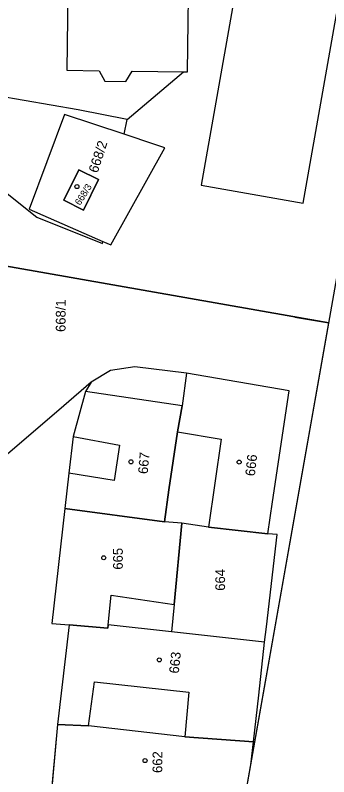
# Model space of a CAD drawing. Extents: x -534481 to -534262, y -1190577 to -1190138.
# Drawn here: x -534325.5 to -534298.1, y -1190410 to -1190343.4 of the extents above; entities that cross this region are included whole.
import ezdxf

# ---------------------------------------------------------------- set-up
doc = ezdxf.new("R2010")
doc.units = 0
for name, color, linetype in [('Definiční body', 7, 'Continuous'), ('Polygon budovy', 7, 'Continuous'), ('Polygon parcely', 7, 'Continuous'), ('Vrstva 30', 7, 'Continuous'), ('Vrstva 43', 7, 'Continuous'), ('Vrstva 46', 7, 'Continuous'), ('Značky bodu BP', 7, 'Continuous')]:
    doc.layers.add(name, color=color, linetype=linetype)

msp = doc.modelspace()

# ---------------------------------------------------------------- linework, layer by layer
at = {"layer": 'Definiční body'}
for p, q in [((-534315.98, -1190353.76), (-534315.73, -1190352.48)), ((-534310.54, -1190374.65), (-534315.06, -1190374.11)), ((-534310.54, -1190374.65), (-534310.94, -1190377.52)), ((-534301.59, -1190376.19), (-534310.54, -1190374.65)), ((-534312.48, -1190387.67), (-534321.18, -1190386.48)), ((-534310.97, -1190387.76), (-534312.48, -1190387.67)), ((-534310.97, -1190387.76), (-534311.63, -1190394.88)), ((-534311.63, -1190394.88), (-534311.85, -1190397.27)), ((-534320.78, -1190396.67), (-534321.81, -1190405.38)), ((-534303.73, -1190398.17), (-534311.85, -1190397.27)), ((-534321.81, -1190405.38), (-534322.86, -1190416.77))]:
    msp.add_line(p, q, dxfattribs=at)
for points in [[(-534315.73, -1190352.48), (-534310.81, -1190348.3), (-534310.45, -1190348.3), (-534310.32, -1190337.38), (-534310.32, -1190337.25)], [(-534315.73, -1190352.48), (-534320, -1190351.64), (-534327.1, -1190350.42), (-534332.53, -1190349.48)], [(-534315.98, -1190353.76), (-534321.21, -1190352.03), (-534324.29, -1190360.33), (-534317.85, -1190363.15)], [(-534332.65, -1190353.81), (-534323.62, -1190361.03), (-534317.88, -1190363.31), (-534317.85, -1190363.15)], [(-534317.85, -1190363.15), (-534317.16, -1190363.45), (-534312.43, -1190354.94), (-534313.32, -1190354.65), (-534315.98, -1190353.76)], [(-534318.22, -1190357.73), (-534319.55, -1190360.4), (-534321.26, -1190359.54), (-534319.94, -1190356.87), (-534318.22, -1190357.73)], [(-534315.06, -1190374.11), (-534317.18, -1190374.42), (-534318.86, -1190375.44)], [(-534318.86, -1190375.44), (-534321.27, -1190377.51), (-534326.78, -1190382.26), (-534328.4, -1190383.66)], [(-534318.86, -1190375.44), (-534319.37, -1190376.25), (-534320.44, -1190380.21), (-534320.81, -1190383.39), (-534321.18, -1190386.48)], [(-534303.44, -1190388.7), (-534303.03, -1190385.92), (-534301.59, -1190376.19)], [(-534310.94, -1190377.52), (-534311.35, -1190379.79), (-534312.08, -1190384.85), (-534312.48, -1190387.67)], [(-534321.18, -1190386.48), (-534322.3, -1190396.55), (-534320.78, -1190396.67)], [(-534303.44, -1190388.7), (-534308.63, -1190388.11), (-534310.97, -1190387.76)], [(-534303.73, -1190398.17), (-534303.58, -1190396.85), (-534302.64, -1190388.78), (-534303.44, -1190388.7)], [(-534311.85, -1190397.27), (-534317.4, -1190396.66), (-534317.42, -1190396.96), (-534320.78, -1190396.67)], [(-534304.7, -1190406.9), (-534304.25, -1190402.82), (-534303.73, -1190398.17)], [(-534304.7, -1190406.9), (-534310.69, -1190406.47), (-534319.12, -1190405.49), (-534321.81, -1190405.38)], [(-534304.949, -1190408.92), (-534304.7, -1190406.9)]]:
    msp.add_lwpolyline(points, dxfattribs=at)
at = {"layer": 'Polygon parcely'}
msp.add_line((-534306.696, -1190418.823), (-534304.949, -1190408.92), dxfattribs=at)
for points in [[(-534320.89, -1190337.07), (-534320.88, -1190337.18), (-534325.2, -1190337.17), (-534325.09, -1190341.34), (-534320.9, -1190341.35), (-534320.99, -1190348.17), (-534318.18, -1190348.21), (-534317.67, -1190349.12), (-534315.85, -1190349.15), (-534315.3, -1190348.25), (-534310.81, -1190348.3), (-534310.45, -1190348.3), (-534310.32, -1190337.38)], [(-534321.26, -1190359.54), (-534319.55, -1190360.4), (-534318.22, -1190357.73), (-534319.94, -1190356.87)], [(-534311.35, -1190379.79), (-534307.52, -1190380.43), (-534308.63, -1190388.11), (-534303.44, -1190388.7), (-534303.03, -1190385.92), (-534301.59, -1190376.19), (-534310.54, -1190374.65), (-534310.94, -1190377.52)], [(-534316.87, -1190384.03), (-534320.81, -1190383.39), (-534321.18, -1190386.48), (-534312.48, -1190387.67), (-534312.08, -1190384.85), (-534311.35, -1190379.79), (-534310.94, -1190377.52), (-534319.37, -1190376.25), (-534320.44, -1190380.21), (-534316.39, -1190380.95)], [(-534322.3, -1190396.55), (-534320.78, -1190396.67), (-534317.42, -1190396.96), (-534317.4, -1190396.66), (-534317.14, -1190394.07), (-534311.63, -1190394.88), (-534310.97, -1190387.76), (-534312.48, -1190387.67), (-534321.18, -1190386.48)], [(-534317.4, -1190396.66), (-534317.42, -1190396.96), (-534320.78, -1190396.67), (-534321.81, -1190405.38), (-534319.12, -1190405.49), (-534318.59, -1190401.64), (-534310.36, -1190402.55), (-534310.69, -1190406.47), (-534304.7, -1190406.9), (-534304.25, -1190402.82), (-534303.73, -1190398.17), (-534311.85, -1190397.27)]]:
    msp.add_lwpolyline(points, close=True, dxfattribs=at)
msp.add_lwpolyline([(-534304.949, -1190408.92), (-534304.7, -1190406.9), (-534310.69, -1190406.47), (-534319.12, -1190405.49), (-534321.81, -1190405.38), (-534322.86, -1190416.77), (-534319.66, -1190417.17), (-534318.89, -1190410.64), (-534311.23, -1190411.47), (-534311.53, -1190414.36), (-534313.6, -1190414.13), (-534314.01, -1190417.87), (-534306.696, -1190418.823)], dxfattribs=at)
at = {"layer": 'Vrstva 30'}
msp.add_line((-534316.367, -1190473.675), (-534298.134, -1190370.27), dxfattribs=at)
for points in [[(-534407.912, -1190137.674), (-534480.845, -1190551.293), (-534334.601, -1190577.08), (-534261.668, -1190163.461)], [(-534279.901, -1190266.866), (-534426.145, -1190241.079), (-534444.378, -1190344.484), (-534298.134, -1190370.27)], [(-534298.134, -1190370.27), (-534444.378, -1190344.484), (-534462.611, -1190447.888), (-534316.367, -1190473.675)]]:
    msp.add_lwpolyline(points, dxfattribs=at)
at = {"layer": 'Vrstva 43'}
msp.add_line((-534301.089, -1190369.749), (-534298.134, -1190370.27), dxfattribs=at)
msp.add_lwpolyline([(-534480.845, -1190551.293), (-534334.601, -1190577.08), (-534261.668, -1190163.461)], dxfattribs=at)
at = {"layer": 'Vrstva 46'}
for centre in [(-534320.115, -1190358.344), (-534315.399, -1190382.411), (-534305.954, -1190382.439), (-534317.776, -1190390.802), (-534312.925, -1190399.727), (-534314.17, -1190408.54)]:
    msp.add_circle(centre, 0.175, dxfattribs=at)
at = {"layer": 'Značky bodu BP'}
msp.add_lwpolyline([(-534300.378, -1190359.794), (-534285.593, -1190275.942), (-534294.476, -1190274.376), (-534309.262, -1190358.228)], close=True, dxfattribs=at)

# ---------------------------------------------------------------- texts
at = {"layer": 'Polygon budovy'}
for s, height, rotation, p in [('668/2', 0.85, 72, (-534318.318, -1190357.208)), ('668/3', 0.595, 58, (-534319.84, -1190360.033)), ('668/1', 0.85, 90, (-534321.107, -1190371.053)), ('667', 0.85, 85, (-534313.939, -1190383.5)), ('666', 0.85, 84, (-534304.581, -1190383.689)), ('665', 0.85, 90, (-534316.112, -1190391.838)), ('664', 0.85, 90, (-534307.185, -1190393.684)), ('663', 0.85, 84, (-534311.233, -1190400.957)), ('662', 0.85, 90, (-534312.662, -1190409.616))]:
    msp.add_text(s, height=height, rotation=rotation, dxfattribs=at).set_placement(p)

doc.saveas('drawing.dxf')
